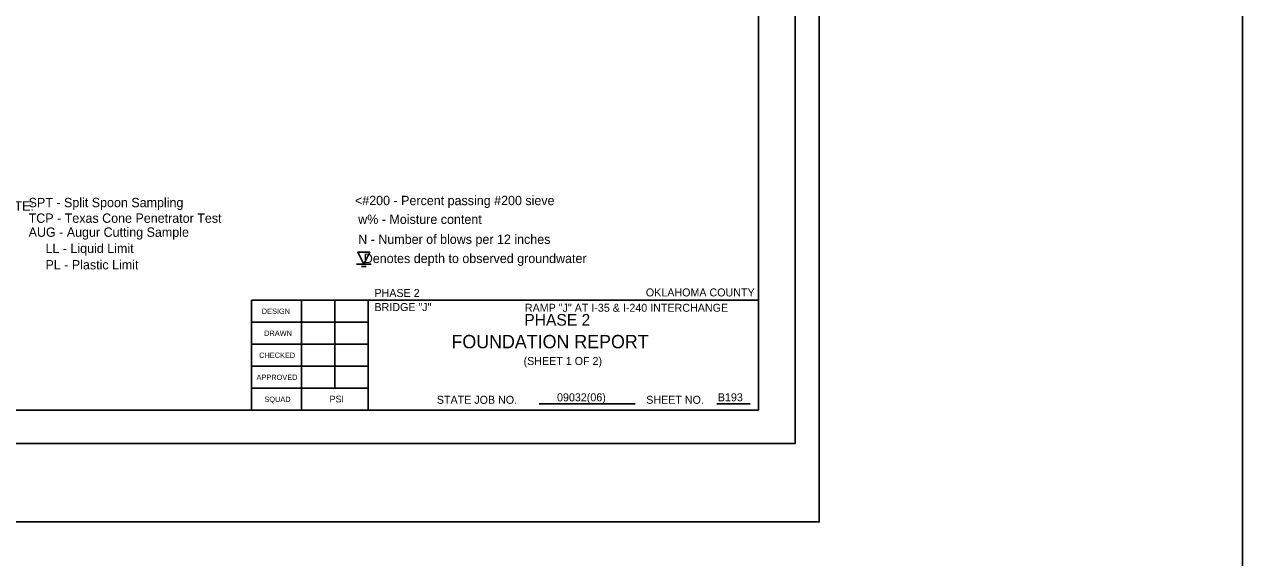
# Model space of a CAD drawing. Extents: x 2150148.6 to 2150220.1, y 143803.7 to 143875.1.
# Drawn here: x 2150195.7 to 2150220.06, y 143834.87 to 143845.54 of the extents above; entities that cross this region are included whole.
import ezdxf

# ---------------------------------------------------------------- set-up
doc = ezdxf.new("R2010")
doc.units = 0
for name, color, linetype in [('Default', 7, 'Continuous'), ('S', 7, 'Continuous'), ('SHT_Plot_Shape_Full', 7, 'Continuous'), ('SHT_Plot_Shape_Half', 7, 'Continuous'), ('SHT_Sheet_Border', 7, 'Continuous'), ('SHT_Standard_Sheet_Lines', 7, 'Continuous'), ('SHT_Standard_Sheet_Txt', 7, 'Continuous'), ('T', 7, 'Continuous'), ('T-Title', 7, 'Continuous'), ('Text', 7, 'Continuous')]:
    doc.layers.add(name, color=color, linetype=linetype)

# ---------------------------------------------------------------- blocks, each defined once
blk = doc.blocks.new('DGRFC_WTLEV1')
at = {"layer": 'Default'}
for points in [[(-0.0127, 0), (0.0127, 0)], [(0, 0), (0.0106, 0.0212), (-0.0106, 0.0212), (0, 0)], [(-0.0042, -0.0042), (0.0042, -0.0042)]]:
    blk.add_lwpolyline(points, dxfattribs=at)

msp = doc.modelspace()

# ---------------------------------------------------------------- linework, layer by layer
at = {"layer": 'S'}
msp.add_lwpolyline([(2150160.321, 143875.14), (2150220.06, 143875.14), (2150220.06, 143803.708), (2150160.321, 143803.708)], close=True, dxfattribs=at)
at = {"layer": 'SHT_Plot_Shape_Full'}
msp.add_lwpolyline([(2150163.596, 143867.587), (2150211.596, 143867.587), (2150211.596, 143835.587), (2150163.596, 143835.587)], close=True, dxfattribs=at)
at = {"layer": 'SHT_Plot_Shape_Half'}
msp.add_lwpolyline([(2150165.779, 143866.487), (2150211.112, 143866.487), (2150211.112, 143837.154), (2150165.779, 143837.154)], close=True, dxfattribs=at)
at = {"layer": 'SHT_Sheet_Border'}
for p, q in [((2150200.246, 143837.82), (2150200.246, 143840.02)), ((2150200.246, 143840.02), (2150210.379, 143840.02)), ((2150202.579, 143837.82), (2150202.579, 143840.021))]:
    msp.add_line(p, q, dxfattribs=at)
msp.add_lwpolyline([(2150210.379, 143837.82), (2150168.379, 143837.82), (2150168.379, 143865.82), (2150210.379, 143865.82)], close=True, dxfattribs=at)
at = {"layer": 'SHT_Standard_Sheet_Lines'}
for p, q in [((2150201.246, 143837.82), (2150201.246, 143840.021)), ((2150201.912, 143838.261), (2150201.912, 143840.021)), ((2150205.993, 143837.949), (2150207.914, 143837.949)), ((2150209.546, 143837.949), (2150210.216, 143837.949))]:
    msp.add_line(p, q, dxfattribs=at)
for points in [[(2150202.579, 143839.58), (2150200.246, 143839.58)], [(2150202.579, 143839.14), (2150200.246, 143839.14)], [(2150202.579, 143838.7), (2150200.246, 143838.7)], [(2150202.579, 143838.26), (2150200.246, 143838.26)]]:
    msp.add_lwpolyline(points, dxfattribs=at)

# ---------------------------------------------------------------- block references
at = {"layer": 'Default', "xscale": 11.338531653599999, "yscale": 11.338531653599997}
msp.add_blockref('DGRFC_WTLEV1', (2150202.489, 143840.741), dxfattribs=at)

# ---------------------------------------------------------------- texts
at = {"layer": 'Defpoints'}
msp.add_text('PHASE 2', height=0.2333, dxfattribs=at).set_placement((2150205.698, 143839.512))
at = {"layer": 'SHT_Standard_Sheet_Txt'}
for s, height, p in [('DESIGN', 0.1067, (2150200.449, 143839.747)), ('DRAWN', 0.1067, (2150200.496, 143839.307)), ('CHECKED', 0.1067, (2150200.396, 143838.867)), ('APPROVED', 0.1067, (2150200.344, 143838.426)), ('SQUAD', 0.1067, (2150200.501, 143837.986)), ('STATE JOB NO.', 0.16, (2150203.949, 143837.949)), ('SHEET NO. ', 0.16, (2150208.135, 143837.949))]:
    msp.add_text(s, height=height, dxfattribs=at).set_placement(p)
at = {"layer": 'T'}
for s, height, p in [('PHASE 2', 0.16, (2150202.702, 143840.086)), ('OKLAHOMA COUNTY', 0.16, (2150208.128, 143840.097)), ('BRIDGE "J"', 0.16, (2150202.702, 143839.804)), ('RAMP "J" AT I-35 & I-240 INTERCHANGE', 0.16, (2150205.709, 143839.79)), ('(SHEET 1 OF 2)', 0.16, (2150205.683, 143838.725)), ('PSI', 0.1333, (2150201.805, 143837.978)), ('09032(06)', 0.16, (2150206.352, 143837.999)), ('B193', 0.16, (2150209.567, 143837.999))]:
    msp.add_text(s, height=height, dxfattribs=at).set_placement(p)
at = {"layer": 'T-Title'}
msp.add_text('FOUNDATION REPORT', height=0.26667, dxfattribs=at).set_placement((2150204.241, 143839.06))
at = {"layer": 'Text'}
for s, height, p in [(' <#200 - Percent passing #200 sieve', 0.18667, (2150202.243, 143841.922)), ('NOTE:', 0.1867, (2150195.13, 143841.814)), ('    SPT - Split Spoon Sampling', 0.18667, (2150195.51, 143841.881)), ('    TCP - Texas Cone Penetrator Test', 0.18667, (2150195.51, 143841.569)), ('w% - Moisture content', 0.18667, (2150202.377, 143841.546)), ('    AUG - Augur Cutting Sample', 0.18667, (2150195.51, 143841.289)), (' LL - Liquid Limit', 0.18667, (2150196.055, 143840.965)), ('N - Number of blows per 12 inches', 0.18667, (2150202.377, 143841.147)), ('    Denotes depth to observed groundwater', 0.18667, (2150202.211, 143840.764)), (' PL - Plastic Limit', 0.18667, (2150196.055, 143840.637))]:
    msp.add_text(s, height=height, dxfattribs=at).set_placement(p)

doc.saveas('drawing.dxf')
